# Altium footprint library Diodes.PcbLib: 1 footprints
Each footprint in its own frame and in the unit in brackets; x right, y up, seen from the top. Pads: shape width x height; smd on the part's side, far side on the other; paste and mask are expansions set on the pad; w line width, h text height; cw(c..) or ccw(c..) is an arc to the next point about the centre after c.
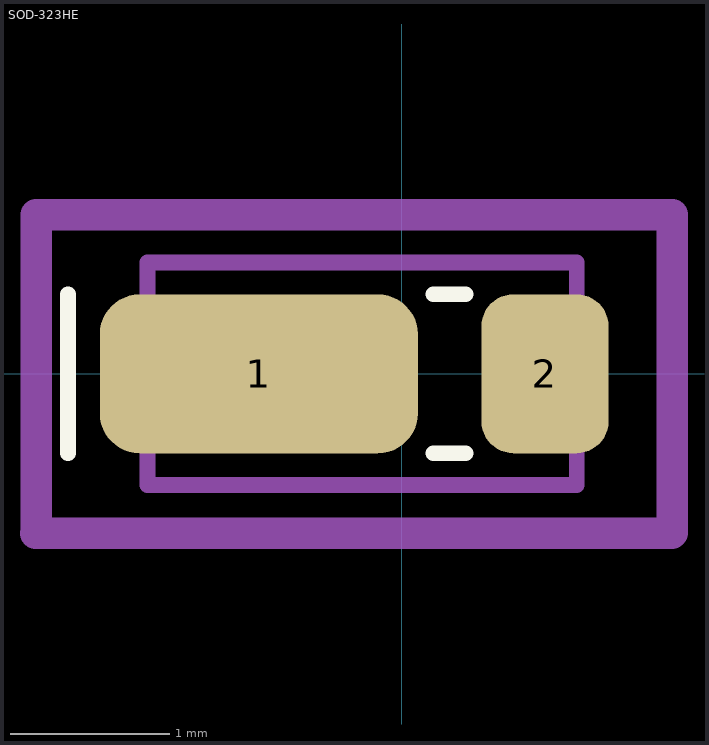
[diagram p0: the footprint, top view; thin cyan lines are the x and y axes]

## SOD-323HE [mm]
height 0.75
pads (2):
  rrect50% 2x1 smd: 1(-0.9,0)
  rrect50% 0.8x1 smd: 2(0.9,0)
Top Overlay:
  lines w0.1: -2.1,-0.5 -2.1,0.5 ; 0.2,-0.5 0.4,-0.5 ; 0.2,0.5 0.4,0.5
Mechanical 13:
  lines w0.1: -1.6,-0.7 1.1,-0.7 1.1,0.7 -1.6,0.7 -1.6,-0.7
Component Courtyard:
  lines w0.2: 1.698,-1.003 -2.302,-1.003 -2.3,-1 -2.3,1 1.7,1 1.7,-1
3D body "SOD_SS13HE_ONS.step": height 0.76, standoff 0, extent -1.596,-0.698 1.096,0.698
